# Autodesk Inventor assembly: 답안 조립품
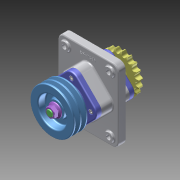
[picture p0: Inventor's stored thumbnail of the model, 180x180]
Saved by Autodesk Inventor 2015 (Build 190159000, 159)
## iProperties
Created: 2026-07
Part Number: 답안 조립품
Document SubType Name: Assembly
Designer: USER
Author: USER
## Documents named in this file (12)
- C:\Users\USER\Downloads\760705V1011\답안 조립품.iam
- C:\Users\USER\Downloads\760705V1011\본체.ipt
- C:\Users\USER\Downloads\760705V1011\가져온 구성요소\6각 구멍붙이 볼트 M6x16\6각 구멍붙이 볼트 M6x16.ipt
- C:\Users\USER\Downloads\760705V1011\가져온 구성요소\6각 플랜지 너트 M16\6각 플랜지 너트 M16.ipt
- C:\Users\USER\Downloads\760705V1011\가져온 구성요소\V-벨트풀리\V-벨트풀리.ipt
- C:\Users\USER\Downloads\760705V1011\가져온 구성요소\깊은 홈 볼 베어링 6206\깊은 홈 볼 베어링 6206.ipt
- C:\Users\USER\Downloads\760705V1011\가져온 구성요소\오일 실 30 45 8\오일 실 30 45 8.ipt
- C:\Users\USER\Downloads\760705V1011\가져온 구성요소\체인 스프로킷\체인 스프로킷.ipt
- C:\Users\USER\Downloads\760705V1011\가져온 구성요소\축\축.ipt
- C:\Users\USER\Downloads\760705V1011\가져온 구성요소\칼라\칼라.ipt
- C:\Users\USER\Downloads\760705V1011\가져온 구성요소\커버\커버.ipt
- C:\Users\USER\Downloads\760705V1011\가져온 구성요소\평행 키 6x6x20\평행 키 6x6x20.ipt
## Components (11 placed, 3 different names)
1. 6각 플랜지 너트 M16:1
2. V-벨트풀리:1
3. 6각 플랜지 너트 M16:2
4. 6각 구멍붙이 볼트 M6x16:1
5. 6각 구멍붙이 볼트 M6x16:3
6. 6각 구멍붙이 볼트 M6x16:4
7. 6각 구멍붙이 볼트 M6x16:5
8. 6각 구멍붙이 볼트 M6x16:2
9. 6각 구멍붙이 볼트 M6x16:6
10. 6각 구멍붙이 볼트 M6x16:7
11. 6각 구멍붙이 볼트 M6x16:8
